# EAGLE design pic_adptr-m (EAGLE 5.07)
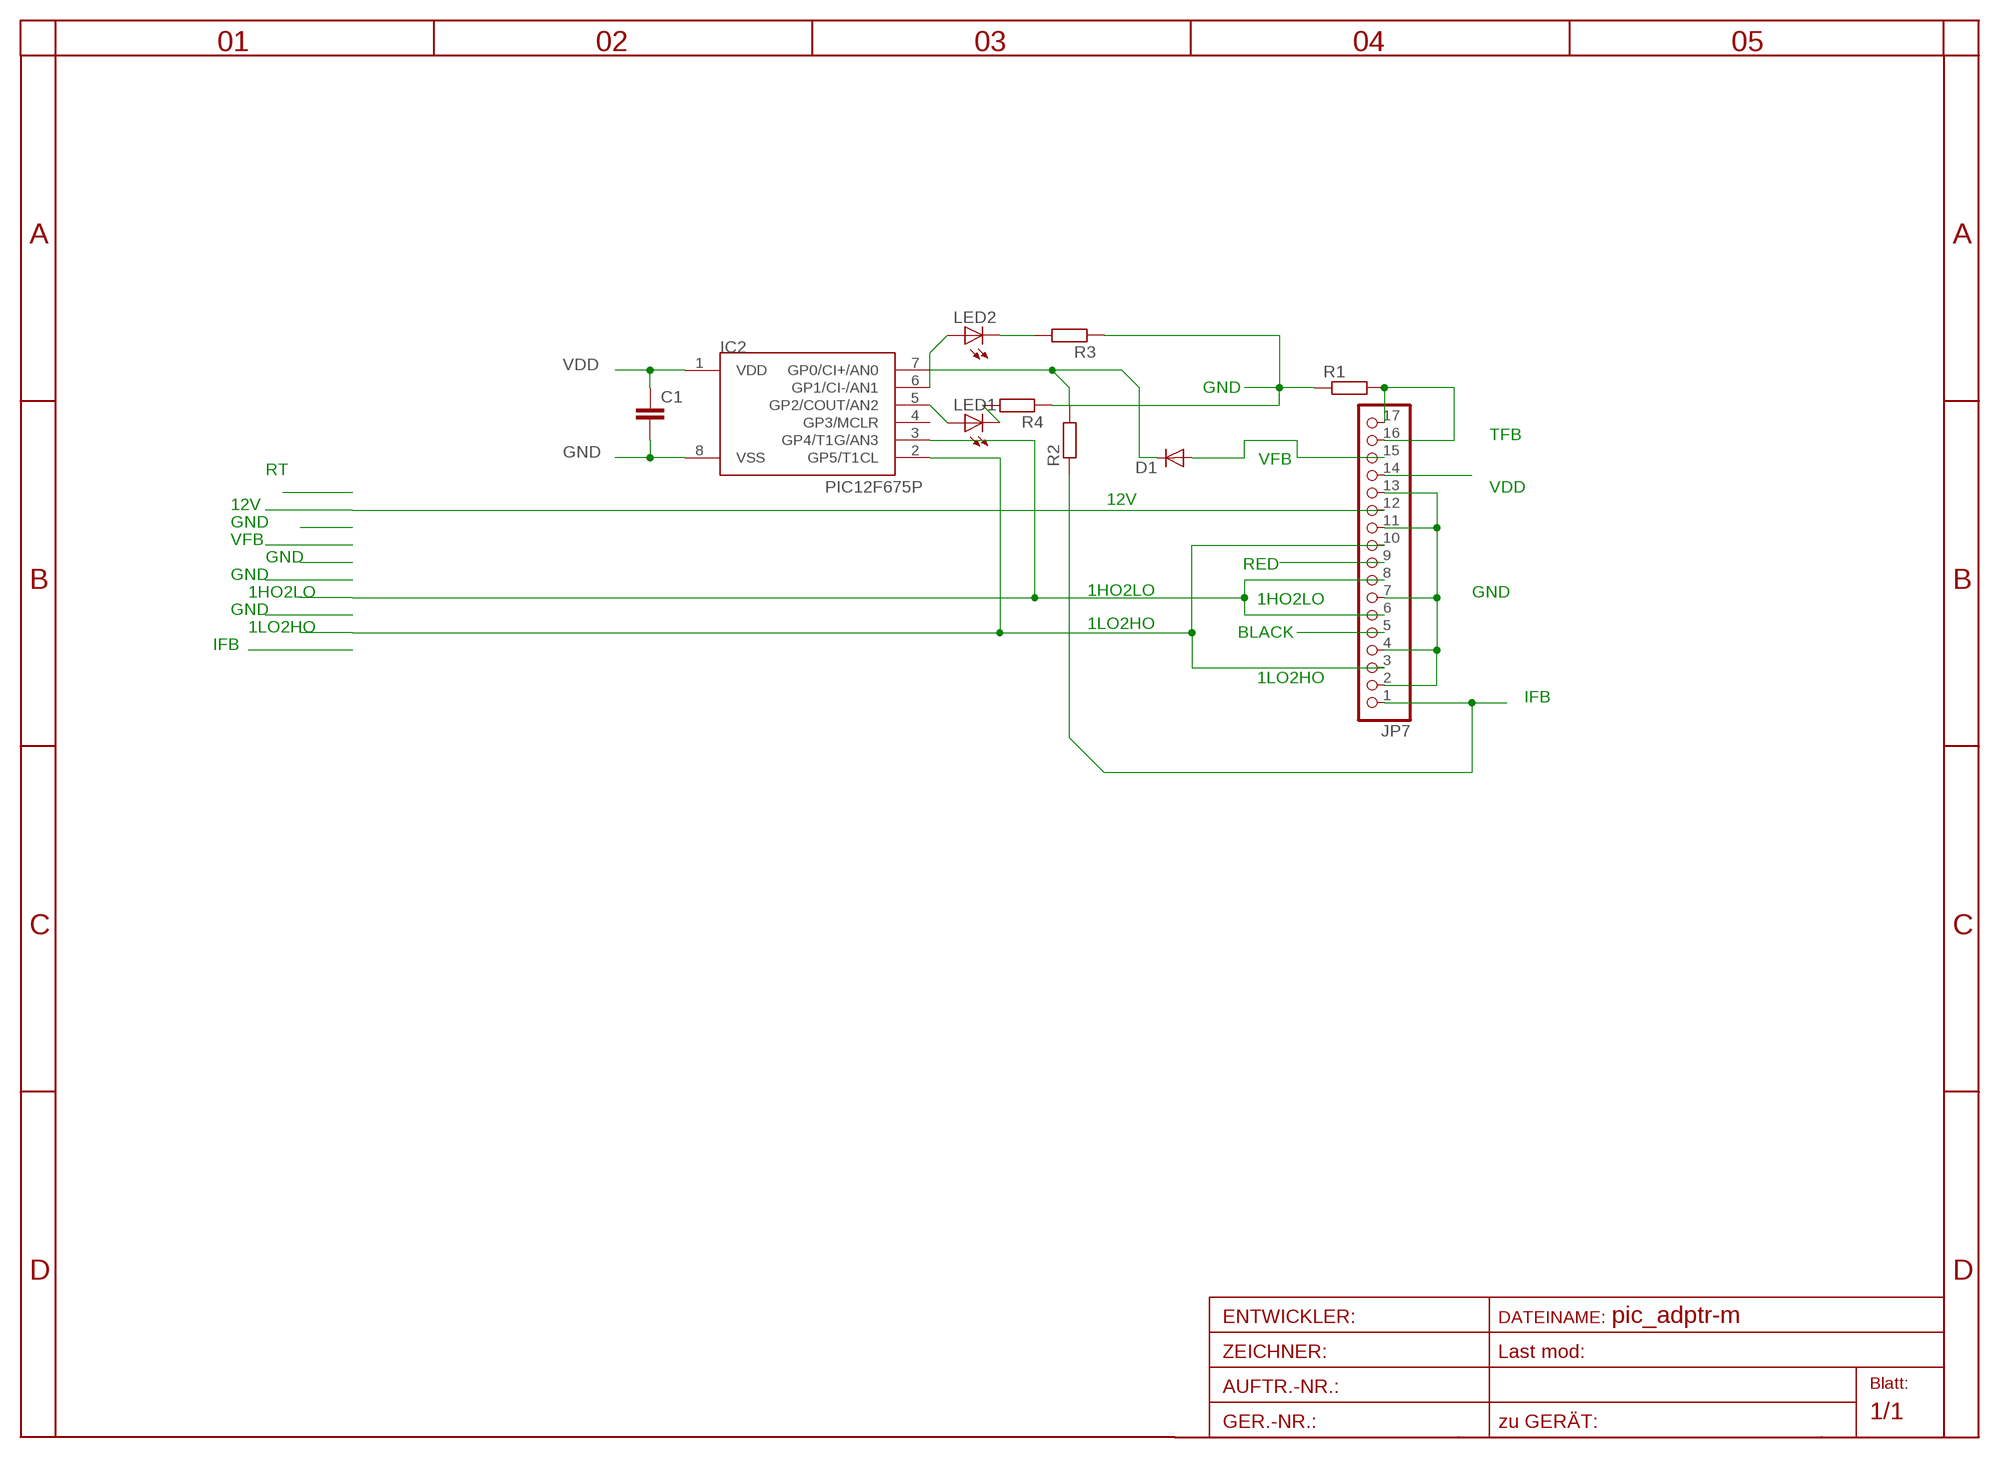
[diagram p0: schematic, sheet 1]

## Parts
C1  C-EUC0805  [C0805]
D1  DIODE-MINIMELF  [MINIMELF]
IC2  PIC12F675P  [DIL8]
JP7  PINHD-1X17  [1X17]
LED1  LEDCHIPLED_1206  [CHIPLED_1206]
LED2  LEDCHIPLED_1206  [CHIPLED_1206]
R1  R-EU_R1206  [R1206]
R2  R-EU_R0805  [R0805]
R3  R-EU_R0805  [R0805]
R4  R-EU_R0805  [R0805]

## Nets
1HO2LO: IC2.3(GP4/T1G/AN3) JP7.6 JP7.8
1LO2HO: IC2.2(GP5/T1CL) JP7.3 JP7.10
12V: JP7.12
BLACK: JP7.5
GND: C1.2 IC2.8(VSS) JP7.2 JP7.4 JP7.7 JP7.11 JP7.13 R1.1 R3.1 R4.1
IFB: JP7.1 R2.1
N$1: IC2.5(GP2/COUT/AN2) LED1.A
N$2: LED1.C R4.2
N$3: IC2.6(GP1/CI-/AN1) LED2.A
N$4: LED2.C R3.2
N$5: D1.C IC2.7(GP0/CI+/AN0) R2.2
RED: JP7.9
TFB: JP7.16 JP7.17 R1.2
VDD: C1.1 IC2.1(VDD) JP7.14
VFB: D1.A JP7.15
Unconnected: IC2.4(GP3/MCLR)

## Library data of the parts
C1 = rcl:C-EU: CAPACITOR, European symbol
D1 = diode:DIODE-: DIODE
IC2 = microchip-5:PIC12F6*: uPC nW 1k Program Flash memory 2x Timer Comparator 10b A/D converter/ 4xIN
JP7 = pinhead:PINHD-1X17: PIN HEADER
LED1 LED2 = led:LED: LED
R1-R4 = rcl:R-EU_: RESISTOR, European symbol

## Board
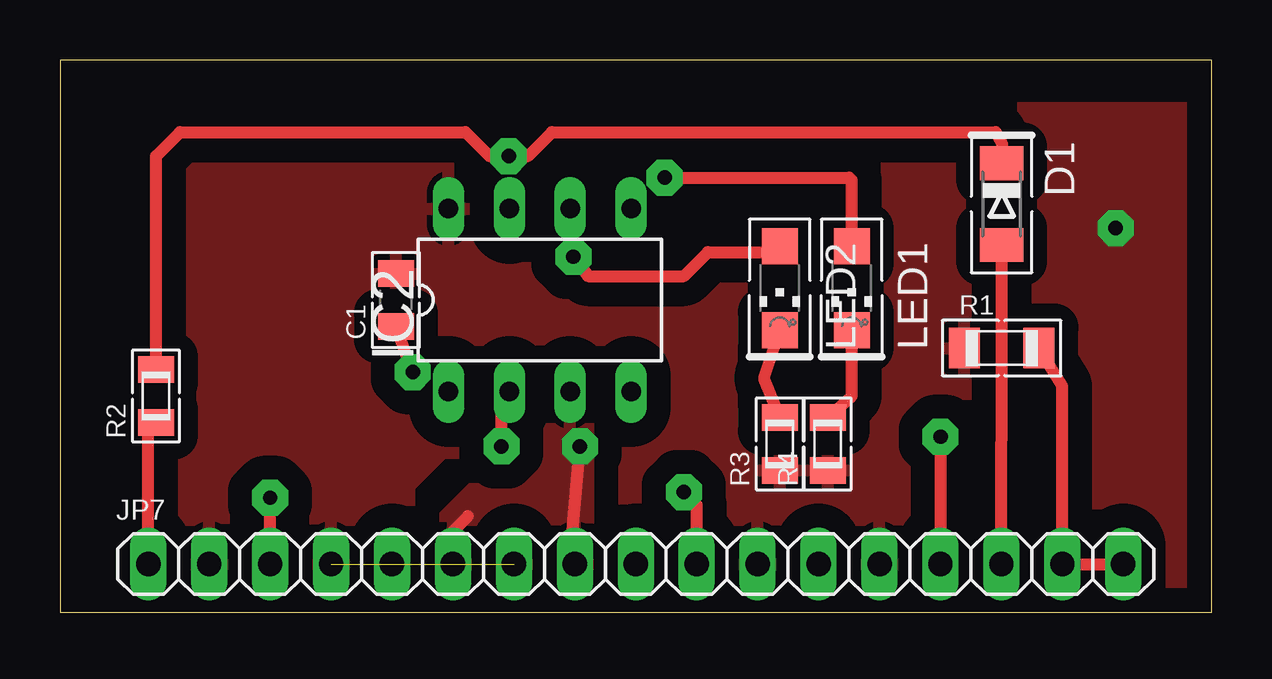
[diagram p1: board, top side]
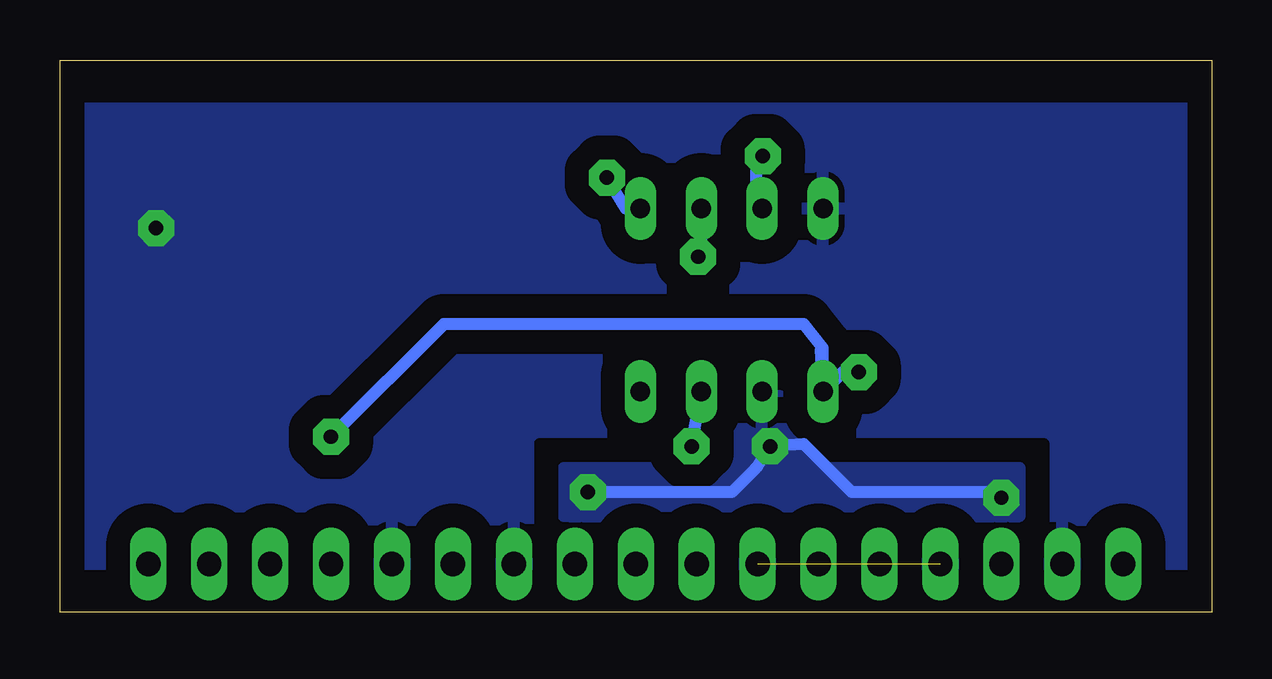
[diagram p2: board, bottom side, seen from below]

Size 48 x 23 mm. Coordinates in mm from the lower left corner, seen from the top.
Outline: 0,0 48,0 48,23 0,23 0,0
Copper layers (1*16): Top 0.035mm / dielectric 1.5mm / Bottom 0.035mm
Design rules "default *": minimum track width 10mil, minimum drill 20mil, track to track 8mil, track to pad 8mil, pad to pad 8mil, via to via 8mil, smd to smd 8mil, copper to edge 40mil, drill to drill 8mil, minimum pad ring 10mil, minimum via ring 8mil, stop-mask expansion 4mil, vias tented up to drill 0mil, thermal gap 10mil

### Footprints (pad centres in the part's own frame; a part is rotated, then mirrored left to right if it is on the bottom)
C0805 = smd 1.1 x 1.5: 1 -1.1,0; 2 1.1,0
MINIMELF = smd 1.4 x 1.8: A 1.7,0; C -1.7,0
DIL8 = drill 0.8 long: 1 -3.81,-3.81; 2 -1.27,-3.81; 3 1.27,-3.81; 4 3.81,-3.81; 5 3.81,3.81; 6 1.27,3.81; 7 -1.27,3.81; 8 -3.81,3.81
1X17 = drill 1.016 long: 1 -20.32,0; 2 -17.78,0; 3 -15.24,0; 4 -12.7,0; 5 -10.16,0; 6 -7.62,0; 7 -5.08,0; 8 -2.54,0; 9 0,0; 10 2.54,0; 11 5.08,0; 12 7.62,0; 13 10.16,0; 14 12.7,0; 15 15.24,0; 16 17.78,0; 17 20.32,0
CHIPLED_1206 = smd 1.5 x 1.5: A 0,-1.75; C 0,1.75
R1206 = smd 1.3 x 1.7: 1 -1.55,0; 2 1.55,0
R0805 = smd 1.1 x 1.5: 1 -1.1,0; 2 1.1,0

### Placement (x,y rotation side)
C1  14,13 90 top
D1  39.25,17 270 top
IC2  20,13 0 top
JP7  24,2 0 top
LED1  33,13.5 180 top
LED2  30,13.5 180 top
R1  39.25,11 0 top
R2  4,9 90 top
R3  30,7 90 top
R4  32,7 90 top

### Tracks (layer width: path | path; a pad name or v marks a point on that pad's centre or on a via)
1HO2LO  (via drill 0.6 pad 1.5)
  Top 0.5: v21.67,6.9 21.27,2.19 JP7.8 | 17,4 16,3 16,2.38 JP7.6
  Bottom 0.5: v21.67,6.9 IC2.3
  pour Top (isolate 1, rank 2): 20,8 22,8 22,1 21,1 21,3 18,3 18,2 17,1 15,1 15,3
1LO2HO  (via drill 0.6 pad 1.5)
  Top 0.5: JP7.3 v8.76,4.76 | JP7.10 26.54,4.46 v26,5 | v18.4,6.9 18.4,8.7 18.8,9.1
  Bottom 0.5: v8.76,4.76 9,5 15,5 16,6 17,7 v18.4,6.9 19,6 20,5 v26,5 | IC2.2 19,8.92 IC2.2
  pour Bottom (isolate 1): 19,9 20,8 20,7 21,6 27,6 27,4 8,4 8,6 16,6 17,7 17,8 18,9
GND  (via drill 0.6 pad 1.5)  (1 unrouted)
  other vias: 44,16
  pour Top (isolate 1, rank 3): 47,21 1,21 1,1 47,1
  pour Bottom (isolate 1, rank 3): 47,21 1,21 1,2 47,2
IFB
  Top 0.5: JP7.1 3.68,7.58 R2.1
N$1  (via drill 0.6 pad 1.5)
  Top 0.5: LED1.A 33,18 32.9,18.1 v25.2,18.1
  Bottom 0.5: IC2.5 24.41,16.81 v25.2,18.1
N$2
  Top 0.5: LED1.C 33,10 33,9 R4.2
N$3  (via drill 0.6 pad 1.5)
  Top 0.5: v21.4,14.8 22,14 26,14 27,15 29.75,15 LED2.A
  Bottom 0.5: IC2.6 21.27,15.27 v21.4,14.8
N$4
  Top 0.5: LED2.C 29.35,9.75 R3.2
N$5  (via drill 0.6 pad 1.5)
  Top 0.5: D1.C 39.25,19.55 39,20 20.5,20 19.5,19 v18.7,19 17.9,19 16.9,20 5,20 4,19 R2.2
  Bottom 0.5: 19,19 19,17.08 IC2.7 | 19,19 v18.7,19 19,19
TFB
  Top 0.5: R1.2 41.78,9.42 JP7.16 JP7.17
VDD  (via drill 0.6 pad 1.5)
  Top 0.5: v36.7,7.3 JP7.14 | v14.7,10 C1.1
  Bottom 0.5: v36.7,7.3 32,12 17,12 16.2,11 16.2,9.48 IC2.1 | IC2.1 16.28,11 | v14.7,10 15.38,10 IC2.1
VFB
  Top 0.5: JP7.15 39.25,12.25 D1.A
